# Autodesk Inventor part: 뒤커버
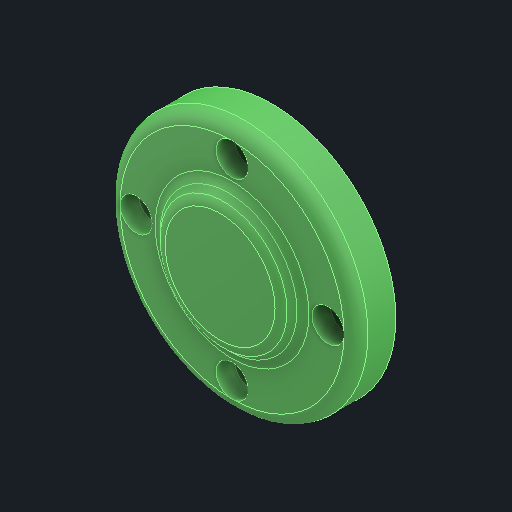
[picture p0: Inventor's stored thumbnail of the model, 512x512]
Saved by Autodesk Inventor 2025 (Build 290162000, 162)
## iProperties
Created: 2025-08
Part Number: 뒤커버
Material: 알루미늄 6061
Document SubType Name: Modeling
Designer: infra005
Density: 2.71 g/cm^3
Appearance: 기본값
Author: jhkim
Sending System: Autodesk Inventor 2026
Preprocessor: ST-DEVELOPER v20.1
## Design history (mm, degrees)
feature "솔리드1"
node "솔리드2"
